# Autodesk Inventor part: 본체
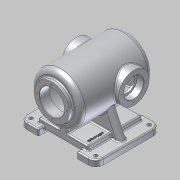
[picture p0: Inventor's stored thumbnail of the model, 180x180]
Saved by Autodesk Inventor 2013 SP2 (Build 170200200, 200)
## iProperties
Created: 2013-06
Part Number: 본체
Document SubType Name: Modeling
Designer: SeoGD™[esajin.kr]
Density: 1 g/cm^3
Material: 일반
Author: SeoGD™[esajin.kr]
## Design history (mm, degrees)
sketch "스케치1"
  geometry: L1 (-100, 85)-(-50, 85); L2 (-50, 85)-(-50, -85); L3 (-50, -85)-(-100, -85); L4 (-100, -85)-(-100, 85); L5 (50, 85)-(100, 85); L6 (100, 85)-(100, -85); L7 (100, -85)-(50, -85); L8 (50, -85)-(50, 85); 3 further points
  constraints: 16 end point, 4 parallel, 2 equal length, 2 horizontal, 2 horizontal alignment, 2 midpoint, 2 perpendicular
  dimensions: "d0" = 100 distance between parallel lines of L8 L2; "d1" = 170 distance of L3.end L1.start; "d3" = 200 distance between parallel lines of L6 L4; "d4" = 50 distance from line of point (0, 0) L2 (= 0.5 x d0)
extrude "돌출1" new body sketch "스케치1" distance "d5" = 16; taper "d6" = 0 deg
node "작업 평면1"
sketch "스케치2"
  geometry: L1 (-65, 70)-(65, 70); L2 (65, 70)-(65, -70); L3 (65, -70)-(-65, -70); L4 (-65, -70)-(-65, 70); 3 further points
  constraints: 8 end point, 2 midpoint, 2 parallel, 1 horizontal, 1 horizontal alignment, 1 perpendicular, 1 vertical alignment
  dimensions: "d8" = 130 distance of L2.end L3.end; "d9" = 140 distance of L1.end L2.end
extrude "돌출2" join sketch "스케치2" distance "d10" = 20; taper "d11" = 0 deg
sketch "스케치3"
  geometry: L1 (-100, 110)-(100, 110); L2 (85, 0)-(-85, 0) reference; L3 (100, 110)-(100, 175); L4 (100, 175)-(-90, 175); L5 (-90, 175)-(-90, 156); L6 (-90, 156)-(-100, 156); L7 (-100, 156)-(-100, 110); L8 (90, 110)-(90, 165); L9 (90, 165)-(-75, 165); L10 (-75, 165)-(-75, 110); L11 (-100, 142.5)-(-75, 142.5); 3 further points
  constraints: 20 end point, 5 perpendicular, 4 parallel, 4 point on line, 2 midpoint, 1 horizontal, 1 vertical alignment
  dimensions: "d12" = 110 distance from line of L2 L1.end; "d13" = 200 distance of L1.start L1.end; "d14" = 130 diameter of L4 L1; "d15" = 92 diameter of L6 L1; "d16" = 10 distance of L5.end L6.end; "d42" = 110 diameter of L9 L1; "d43" = 10 distance between parallel lines of L3 L8; "d44" = 25 distance between parallel lines of L10 L7; "d45" = 65 diameter of L11 L1
revolve "회전1" sketch "스케치3" stored, may be unused: angle "d17" = 90 deg
sketch "스케치4"
  geometry: L1 (-50, 70)-(50, 70) reference; L2 (50, -70)-(-50, -70) reference; L3 (-10, 70)-(-10, -70); L4 (10, -70)-(10, 70); 1 further point
  constraints: 4 end point, 4 point on line, 2 perpendicular
  dimensions: "d18" = 20 distance between parallel lines of L4 L3; "d19" = 10 distance from line of point (0, 0) L3
extrude "돌출3" join sketch "스케치4" stored distance "d20" = 10; taper "d21" = 0 deg
node "작업 평면2"
sketch "스케치5"
  geometry: L1 (-50, -8)-(0, -8) reference; L2 (100, -8)-(150, -8) reference; L3 (-40, -8)-(-8.943, -74.601); L4 (140, -8)-(108.943, -74.601); L5 (-50, 8)-(-50, -8) reference; L6 (150, 8)-(150, -8) reference; A1 r 65 centre (50, -102) between (-8.943, -74.601) and (108.943, -74.601) reference; 1 further point
  constraints: 4 end point, 2 point on circle, 2 point on line, 1 equal length
  dimensions: "d23" = 10 distance from line of L3.start L5; "d24" = 10 distance from line of L4.start L6; "d25" = 25 deg angle of L3 L5
feature "리브1" sketch "스케치5" dims "d26" = 1, "d27" = 20, "d28" = 0
node "작업 평면3"
sketch "스케치6"
  geometry: L1 (100, 156)-(100, 64) reference; C1 r 40 at (-40, 110); 2 further points
  constraints: 1 centre point, 1 horizontal alignment, 1 midpoint
  dimensions: "d37" = 80 diameter of C1; "d38" = 140 distance from line of C1.centre L1
extrude "돌출4" join sketch "스케치6" stored distance "d39" = 10; taper "d40" = 0 deg
hole "구멍1" diameter "d48" = 42; stored, may be unused: countersink angle "d52" = 90 deg, drill point angle "d54" = 118 deg; dims "d46" = 10, "d47" = 10, "d49" = 6, "d50" = 52, "d51" = 18, "d53" = 8
sketch "스케치7"
  geometry: C1 r 40 at (0, 0) reference; 2 further points
  constraints: 1 horizontal alignment
  dimensions: "d55" = 32.5 distance of point (32.5, 0) C1.centre
hole "구멍2" sketch "스케치7" at (32.5, 0) diameter "d56" = 3.242; stored, may be unused: countersink angle "d60" = 90 deg, drill point angle "d62" = 118 deg; dims "d57" = 10, "d58" = 52, "d59" = 18, "d61" = 13
sketch "스케치8"
  geometry: C1 r 46 at (0, 0) reference; 2 further points
  constraints: 1 vertical alignment
  dimensions: "d66" = 39 distance of C1.centre point (0, 39)
hole "구멍3" sketch "스케치8" at (0, 39) diameter "d67" = 3.242; stored, may be unused: countersink angle "d71" = 90 deg, drill point angle "d73" = 118 deg; dims "d68" = 10, "d69" = 52, "d70" = 18, "d72" = 13
fillet "모깎기7" dims "d77" = 20, "d78" = 13, "d79" = 3, "d80" = 10
fillet "모깎기8" dims "d81" = 3
fillet "모깎기9" dims "d82" = 3
fillet "모깎기10" dims "d83" = 3, "d84" = 0.3
chamfer "모따기1" distance "d85" = 1; stored, may be unused: second distance "d86" = 2, angle "d87" = 45 deg
node "작업 평면4"
sketch "스케치10"
  geometry: 5 further points
  constraints: 2 horizontal alignment, 2 vertical alignment
  dimensions: "d90" = 170 distance of point (85, 70) point (-85, 70); "d91" = 140 distance of point (-85, 70) point (-85, -70); "d92" = 70 vertical distance of point (0, 0) point (-85, -70) (= 0.5 x d91); "d93" = 85 horizontal distance of point (0, 0) point (-85, 70) (= 0.5 x d90)
hole "구멍4" sketch "스케치10" at (-85, 70), (85, 70), (85, -70), (-85, -70) diameter "d94" = 10; stored, may be unused: countersink angle "d98" = 90 deg, drill point angle "d100" = 118 deg; dims "d95" = 6, "d96" = 4, "d97" = 2, "d99" = 8
sketch "스케치11"
  geometry: L1 (13, -70)-(62, -70) reference; L2 (65, -67)-(65, -13) reference; 2 further points
  constraints: 1 other
  dimensions: "d101" = 30 distance from line of point (55, -40) L1; "d102" = 10 distance from line of point (55, -40) L2
feature "엠보싱2" sketch "스케치11" dims "d0" = 100, "d1" = 170, "d3" = 200, "d4" = 50 (= 0.5 x d0), "d103" = 1, "d104" = 0
node "솔리드1"
mirror "대칭1"
pattern_circular "원형 패턴1" dims angle "d64" = 360 deg
mirror "대칭3"
pattern_circular "원형 패턴2" dims angle "d75" = 360 deg
other parameters: "d7" = 8, "d36" = -75
